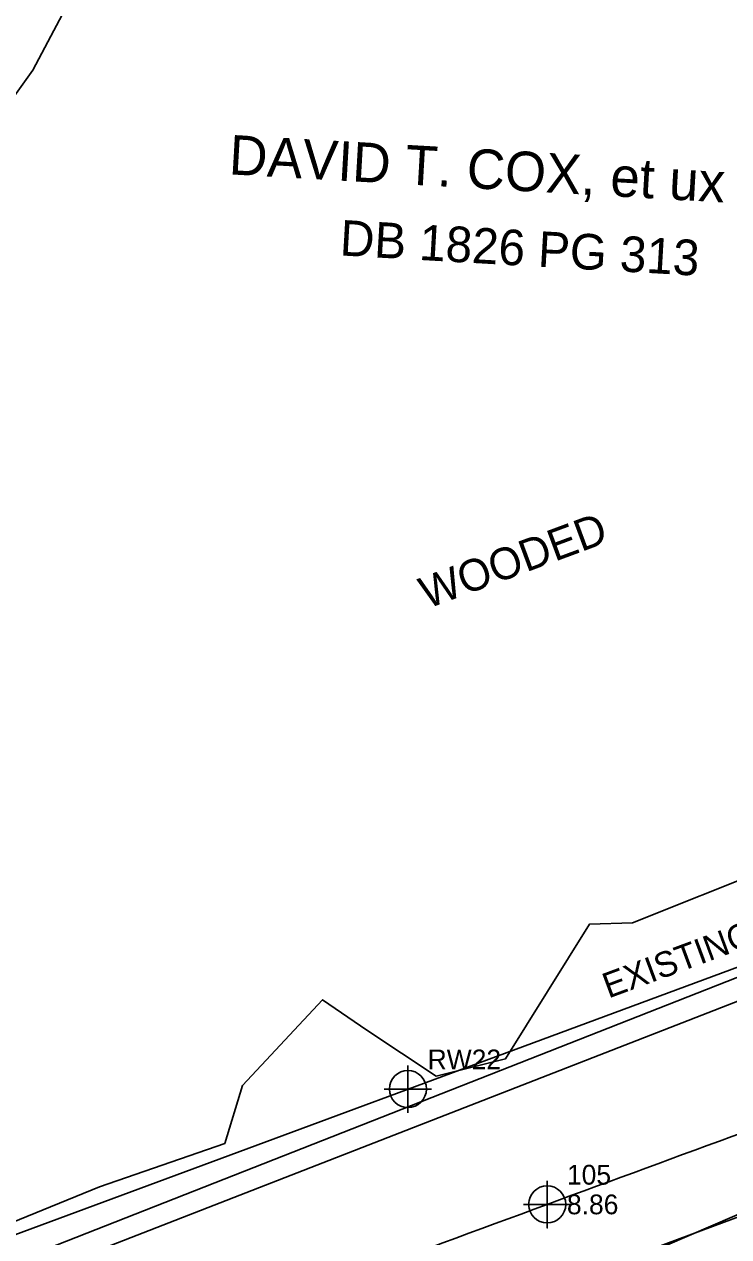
# Model space of a CAD drawing. Extents: x 2597630 to 2605918, y 617194 to 635093.
# Drawn here: x 2603216.8 to 2603305.9, y 618405.5 to 618558.9 of the extents above; entities that cross this region are included whole.
import ezdxf

# ---------------------------------------------------------------- set-up
doc = ezdxf.new("R2010")
doc.units = 0
for name, color, linetype in [('COGO Default Chain', 7, 'Continuous'), ('Cogo Default Point CELL', 7, 'Continuous'), ('COGO Default Point Number', 7, 'Continuous'), ('Exist Horizontal Alignment', 7, 'Continuous'), ('Exist Property Deed Book Text', 7, 'Continuous'), ('Exist Property Owner Text', 7, 'Continuous'), ('Exist Right of Way Line', 7, 'Continuous'), ('Exist Right of Way Line Text', 7, 'Continuous'), ('Exist Roads EOP', 7, 'Continuous'), ('Exist Roads EOP Cogo Elevation', 7, 'Continuous'), ('Exist Roads EOP Cogo Number', 7, 'Continuous'), ('Exist Roads EOP Cogo Point CELL', 7, 'Continuous'), ('Exist Utilities Telephone UG Cable SUE LOS C', 7, 'Continuous'), ('Exist Vegetation Woods Line', 7, 'Continuous'), ('Exist Vegetation Woods Line Text', 7, 'Continuous')]:
    doc.layers.add(name, color=color, linetype=linetype)

# ---------------------------------------------------------------- blocks, each defined once
blk = doc.blocks.new('EXIST ROADS EOP COGO POINT')
at = {"layer": 'Exist Roads EOP Cogo Point CELL'}
blk.add_lwpolyline([(0, 0.06), (0, -0.06), (0, 0), (0.06, 0), (-0.06, 0)], dxfattribs=at)
blk.add_circle((0, 0), 0.0469, dxfattribs=at)
blk = doc.blocks.new('COGO DEFAULT POINT')
at = {"layer": 'Cogo Default Point CELL'}
for points in [[(0, 0.06), (0, 0)], [(-0.06, 0), (0, 0)], [(0, 0), (0.06, 0)], [(0, 0), (0, -0.06)]]:
    blk.add_lwpolyline(points, dxfattribs=at)
blk.add_circle((0, 0), 0.0469, dxfattribs=at)

msp = doc.modelspace()

# ---------------------------------------------------------------- linework, layer by layer
at = {"layer": 'COGO Default Chain'}
for p, q in [((2603088.07, 618326.9), (2603749.85, 618571.99)), ((2603088.07, 618326.9), (2603749.85, 618571.99)), ((2603088.07, 618326.9), (2603749.85, 618571.99)), ((2603088.07, 618326.9), (2603749.85, 618571.99)), ((2603088.07, 618326.9), (2603749.85, 618571.99)), ((2603088.07, 618326.9), (2603749.85, 618571.99)), ((2603012.53, 618281.56), (2603565.53, 618519.59)), ((2603012.53, 618281.56), (2603565.53, 618519.59)), ((2603275.62, 618396.36), (2603404.15, 618443.96)), ((2603088.07, 618326.9), (2603309.42, 618408.88)), ((2603088.07, 618326.9), (2603309.42, 618408.88)), ((2603088.07, 618326.9), (2603309.42, 618408.88))]:
    msp.add_line(p, q, dxfattribs=at)
at = {"layer": 'Exist Horizontal Alignment'}
msp.add_line((2603088.07, 618326.9), (2603749.85, 618571.99), dxfattribs=at)
at = {"layer": 'Exist Right of Way Line'}
msp.add_line((2603077.76, 618354.73), (2603739.55, 618599.82), dxfattribs=at)
at = {"layer": 'Exist Roads EOP'}
for points in [[(2603230.17, 618389.98), (2603282.93, 618409.6), (2603332.77, 618427.87), (2603388.17, 618448.41), (2603437.2, 618466.72), (2603490.78, 618486.53), (2603539.04, 618504.56), (2603597.45, 618526.16), (2603651.05, 618545.97), (2603705.21, 618566.08), (2603762.02, 618587.18), (2603820.33, 618609.16), (2603876.34, 618629.99), (2603934.91, 618652.28), (2603996.41, 618675.57), (2604033.22, 618689.96), (2604052.01, 618697.2)], [(2604034.63, 618668.49), (2603984.89, 618650.12), (2603936.77, 618631.65), (2603888.19, 618613.33), (2603837.77, 618594.26), (2603782.92, 618573.7), (2603731.94, 618554.39), (2603671.13, 618532.17), (2603621.82, 618514.11), (2603561.54, 618491.88), (2603506.42, 618471.29), (2603452.16, 618451.33), (2603398.36, 618431.32), (2603341.43, 618410.35), (2603281.65, 618388.2), (2603223.03, 618366.47), (2603185.72, 618352.61)]]:
    msp.add_spline(points, degree=3, dxfattribs=at)
at = {"layer": 'Exist Utilities Telephone UG Cable SUE LOS C'}
msp.add_line((2603188.1, 618391.59), (2603435.03, 618488.63), dxfattribs=at)
msp.add_lwpolyline([(2603188.81, 618389.27), (2603430.63, 618483.45), (2603435.03, 618488.63)], dxfattribs=at)
at = {"layer": 'Exist Vegetation Woods Line'}
for points in [[(2603113.39, 618393.97), (2603112.18, 618408.84), (2603111.28, 618420.83), (2603112.93, 618431.53), (2603110.4, 618438.25), (2603109.97, 618448), (2603110.03, 618460.15), (2603117.45, 618475.29), (2603125.98, 618486.76), (2603141.38, 618499.63), (2603158.04, 618507.22), (2603170.05, 618512.43), (2603187.99, 618522.1), (2603208.85, 618540.53), (2603217.86, 618553.11), (2603223.51, 618563.79)], [(2603311.03, 618452.15), (2603293.73, 618445.2), (2603288.3, 618445.07), (2603277.67, 618428.02), (2603268.87, 618425.82), (2603260.11, 618431.62), (2603254.53, 618435.48), (2603244.41, 618424.66), (2603242.14, 618417.32), (2603226.29, 618411.81), (2603179.38, 618392.69)]]:
    msp.add_lwpolyline(points, dxfattribs=at)

# ---------------------------------------------------------------- block references
at = {"layer": 'Cogo Default Point CELL', "xscale": 50, "yscale": 50}
msp.add_blockref('COGO DEFAULT POINT', (2603265.31, 618424.19), dxfattribs=at)
at = {"layer": 'Exist Roads EOP Cogo Point CELL', "xscale": 50, "yscale": 50}
msp.add_blockref('EXIST ROADS EOP COGO POINT', (2603282.93, 618409.6), dxfattribs=at)
msp.add_blockref('EXIST ROADS EOP COGO POINT', (2603282.93, 618409.6), dxfattribs=at)

# ---------------------------------------------------------------- texts
at = {"layer": 'COGO Default Point Number'}
msp.add_text('RW22', height=2.5, dxfattribs=at).set_placement((2603267.81, 618426.69))
at = {"layer": 'Exist Property Deed Book Text'}
msp.add_text('DB 1826 PG 313', height=4.5, rotation=356.7403, dxfattribs=at).set_placement((2603256.63, 618529.66))
at = {"layer": 'Exist Property Owner Text'}
msp.add_text('DAVID T. COX, et ux', height=5, rotation=356.7403, dxfattribs=at).set_placement((2603242.6, 618539.92))
at = {"layer": 'Exist Right of Way Line Text'}
msp.add_text('EXISTING R/W VARIES', height=3.2, rotation=20.3221, dxfattribs=at).set_placement((2603290.68, 618435.63))
at = {"layer": 'Exist Roads EOP Cogo Elevation'}
msp.add_text('8.86', height=2.5, dxfattribs=at).set_placement((2603285.43, 618408.35))
at = {"layer": 'Exist Roads EOP Cogo Number'}
msp.add_text('105', height=2.5, dxfattribs=at).set_placement((2603285.43, 618412.1))
at = {"layer": 'Exist Vegetation Woods Line Text'}
msp.add_text('WOODED', height=4, rotation=20.3221, dxfattribs=at).set_placement((2603267.73, 618484.91))

doc.saveas('drawing.dxf')
